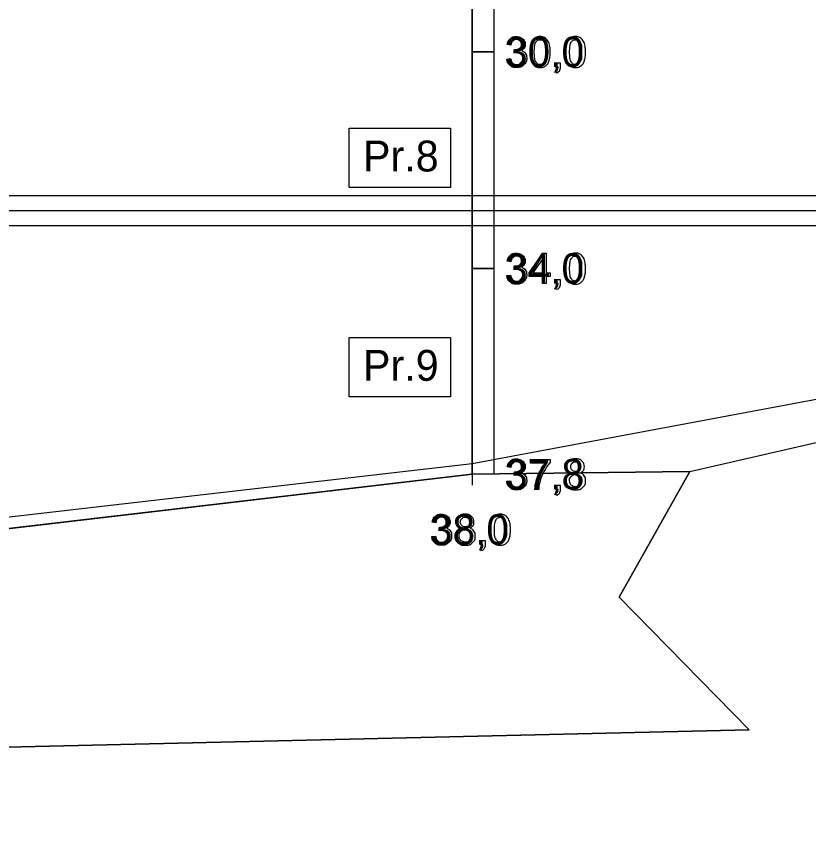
# Model space of a CAD drawing. Extents: x 700746 to 706058, y 6570320 to 6580460.
# Drawn here: x 705325.7 to 705472.1, y 6574755.4 to 6574905.5 of the extents above; entities that cross this region are included whole.
import ezdxf

# ---------------------------------------------------------------- set-up
doc = ezdxf.new("R2010")
doc.units = 0
for name, color, linetype in [('GEOLPUNKT', 7, 'Continuous'), ('GEOLPUNKT_proovid', 7, 'Continuous'), ('Maapind', 7, 'Continuous'), ('PIIR', 7, 'Continuous'), ('Plokid', 7, 'Continuous'), ('Täide', 7, 'Continuous')]:
    doc.layers.add(name, color=color, linetype=linetype)

msp = doc.modelspace()

# ---------------------------------------------------------------- linework, layer by layer
at = {"layer": 'GEOLPUNKT'}
msp.add_line((705409.93, 6574997.46), (705409.93, 6574818.93), dxfattribs=at)
for points in [[(705403.2, 6574811.95), (705402.51, 6574812.08)], [(705403.8, 6574810.56), (705403.87, 6574811.16)], [(705402.44, 6574809.39), (705403.13, 6574809.48)], [(705411.51, 6574807.91), (705411.51, 6574808.69), (705412.29, 6574808.69), (705412.29, 6574807.91)], [(705411.9, 6574807.91), (705411.51, 6574807.91)], [(705411.65, 6574806.8), (705411.46, 6574807.09)]]:
    msp.add_lwpolyline(points, dxfattribs=at)
for points in [[(705402.51, 6574812.08), (705402.64, 6574812.77), (705403.08, 6574813.15), (705403.53, 6574813.53), (705404.19, 6574813.53), (705404.65, 6574813.53), (705405.04, 6574813.33), (705405.43, 6574813.14), (705405.63, 6574812.8), (705405.83, 6574812.46), (705405.83, 6574812.08), (705405.83, 6574811.71), (705405.64, 6574811.42), (705405.44, 6574811.12), (705405.06, 6574810.94), (705405.56, 6574810.83), (705405.83, 6574810.47), (705406.11, 6574810.11), (705406.11, 6574809.57), (705406.11, 6574808.83), (705405.57, 6574808.32), (705405.04, 6574807.81), (705404.22, 6574807.81), (705403.48, 6574807.81), (705403, 6574808.25), (705402.51, 6574808.69), (705402.44, 6574809.39)], [(705407.85, 6574810.95), (705407.42, 6574811.1), (705407.21, 6574811.39), (705407, 6574811.68), (705407, 6574812.09), (705407, 6574812.7), (705407.44, 6574813.11), (705407.88, 6574813.53), (705408.61, 6574813.53), (705409.34, 6574813.53), (705409.79, 6574813.1), (705410.23, 6574812.68), (705410.23, 6574812.07), (705410.23, 6574811.68), (705410.03, 6574811.39), (705409.83, 6574811.1), (705409.41, 6574810.95), (705409.93, 6574810.78), (705410.2, 6574810.4), (705410.47, 6574810.03), (705410.47, 6574809.51), (705410.47, 6574808.79), (705409.96, 6574808.3), (705409.45, 6574807.81), (705408.62, 6574807.81), (705407.79, 6574807.81), (705407.29, 6574808.31), (705406.78, 6574808.8), (705406.78, 6574809.53), (705406.78, 6574810.08), (705407.06, 6574810.44), (705407.33, 6574810.81), (705407.85, 6574810.95)], [(705413.31, 6574810.67), (705413.31, 6574811.66), (705413.51, 6574812.27), (705413.72, 6574812.87), (705414.12, 6574813.2), (705414.52, 6574813.53), (705415.13, 6574813.53), (705415.58, 6574813.53), (705415.92, 6574813.35), (705416.26, 6574813.17), (705416.49, 6574812.83), (705416.71, 6574812.48), (705416.83, 6574811.99), (705416.96, 6574811.5), (705416.96, 6574810.67), (705416.96, 6574809.68), (705416.76, 6574809.08), (705416.55, 6574808.47), (705416.15, 6574808.14), (705415.75, 6574807.81), (705415.13, 6574807.81), (705414.32, 6574807.81), (705413.86, 6574808.39), (705413.31, 6574809.09), (705413.31, 6574810.67)], [(705403.87, 6574811.16), (705403.94, 6574811.16), (705403.98, 6574811.16), (705404.42, 6574811.16), (705404.77, 6574811.39), (705405.13, 6574811.62), (705405.13, 6574812.09), (705405.13, 6574812.47), (705404.87, 6574812.72), (705404.61, 6574812.97), (705404.21, 6574812.97), (705403.81, 6574812.97), (705403.54, 6574812.71), (705403.27, 6574812.46), (705403.2, 6574811.95)], [(705407.71, 6574812.11), (705407.71, 6574811.72), (705407.97, 6574811.46), (705408.22, 6574811.21), (705408.63, 6574811.21), (705409.02, 6574811.21), (705409.28, 6574811.46), (705409.53, 6574811.71), (705409.53, 6574812.07), (705409.53, 6574812.45), (705409.27, 6574812.71), (705409.01, 6574812.97), (705408.62, 6574812.97), (705408.23, 6574812.97), (705407.97, 6574812.71), (705407.71, 6574812.46), (705407.71, 6574812.11)], [(705414.02, 6574810.67), (705414.02, 6574809.29), (705414.34, 6574808.83), (705414.66, 6574808.38), (705415.13, 6574808.38), (705415.61, 6574808.38), (705415.93, 6574808.83), (705416.25, 6574809.29), (705416.25, 6574810.67), (705416.25, 6574812.05), (705415.93, 6574812.51), (705415.61, 6574812.96), (705415.13, 6574812.96), (705414.65, 6574812.96), (705414.37, 6574812.56), (705414.02, 6574812.05), (705414.02, 6574810.67)], [(705403.13, 6574809.48), (705403.25, 6574808.9), (705403.53, 6574808.64), (705403.81, 6574808.38), (705404.22, 6574808.38), (705404.71, 6574808.38), (705405.04, 6574808.72), (705405.38, 6574809.05), (705405.38, 6574809.55), (705405.38, 6574810.02), (705405.07, 6574810.33), (705404.76, 6574810.64), (705404.28, 6574810.64), (705404.09, 6574810.64), (705403.8, 6574810.56)], [(705407.49, 6574809.52), (705407.49, 6574809.23), (705407.62, 6574808.95), (705407.76, 6574808.68), (705408.04, 6574808.53), (705408.31, 6574808.38), (705408.63, 6574808.38), (705409.12, 6574808.38), (705409.44, 6574808.69), (705409.76, 6574809.01), (705409.76, 6574809.5), (705409.76, 6574810), (705409.43, 6574810.32), (705409.1, 6574810.65), (705408.6, 6574810.65), (705408.12, 6574810.65), (705407.8, 6574810.33), (705407.49, 6574810.01), (705407.49, 6574809.52)], [(705411.46, 6574807.09), (705411.68, 6574807.19), (705411.78, 6574807.37), (705411.88, 6574807.56), (705411.9, 6574807.91)], [(705412.29, 6574807.91), (705412.29, 6574807.48), (705412.14, 6574807.21), (705411.98, 6574806.94), (705411.65, 6574806.8)]]:
    msp.add_open_spline(points, degree=3, dxfattribs=at)
at = {"layer": 'GEOLPUNKT_proovid'}
for points in [[(705409.93, 6574948.93), (705413.93, 6574948.93), (705413.93, 6574898.93), (705409.93, 6574898.93)], [(705409.93, 6574898.93), (705413.93, 6574898.93), (705413.93, 6574858.93), (705409.93, 6574858.93)], [(705387.17, 6574884.82), (705405.87, 6574884.82), (705405.87, 6574873.86), (705387.17, 6574873.86)], [(705409.93, 6574858.93), (705413.93, 6574858.93), (705413.93, 6574820.93), (705409.93, 6574820.93)], [(705387.17, 6574846.17), (705405.87, 6574846.17), (705405.87, 6574835.21), (705387.17, 6574835.21)]]:
    msp.add_lwpolyline(points, close=True, dxfattribs=at)
for points in [[(705417.06, 6574900.18), (705416.38, 6574900.3)], [(705417.66, 6574898.78), (705417.74, 6574899.39)], [(705416.31, 6574897.61), (705417, 6574897.7)], [(705425.37, 6574896.13), (705425.37, 6574896.91), (705426.16, 6574896.91), (705426.16, 6574896.13)], [(705425.76, 6574896.13), (705425.37, 6574896.13)], [(705425.52, 6574895.02), (705425.33, 6574895.31)], [(705422.86, 6574856.13), (705422.86, 6574857.47), (705420.43, 6574857.47), (705420.43, 6574858.1), (705422.98, 6574861.73), (705423.54, 6574861.73), (705423.54, 6574858.1), (705424.3, 6574858.1), (705424.3, 6574857.47), (705423.54, 6574857.47), (705423.54, 6574856.13), (705422.86, 6574856.13)], [(705417.06, 6574860.18), (705416.38, 6574860.3)], [(705422.86, 6574858.1), (705422.86, 6574860.63), (705421.1, 6574858.1), (705422.86, 6574858.1)], [(705417.66, 6574858.78), (705417.74, 6574859.39)], [(705416.31, 6574857.61), (705417, 6574857.7)], [(705425.37, 6574856.13), (705425.37, 6574856.91), (705426.16, 6574856.91), (705426.16, 6574856.13)], [(705425.76, 6574856.13), (705425.37, 6574856.13)], [(705425.52, 6574855.02), (705425.33, 6574855.31)], [(705420.7, 6574822.99), (705420.7, 6574823.66), (705424.32, 6574823.66), (705424.32, 6574823.12)], [(705423.44, 6574822.99), (705420.7, 6574822.99)], [(705417.06, 6574822.18), (705416.38, 6574822.3)], [(705417.66, 6574820.78), (705417.74, 6574821.39)], [(705416.31, 6574819.61), (705417, 6574819.7)], [(705422.19, 6574818.13), (705421.48, 6574818.13)], [(705425.37, 6574818.13), (705425.37, 6574818.91), (705426.16, 6574818.91), (705426.16, 6574818.13)], [(705425.76, 6574818.13), (705425.37, 6574818.13)], [(705425.52, 6574817.02), (705425.33, 6574817.31)]]:
    msp.add_lwpolyline(points, dxfattribs=at)
for points in [[(705416.38, 6574900.3), (705416.5, 6574900.99), (705416.95, 6574901.37), (705417.4, 6574901.75), (705418.06, 6574901.75), (705418.52, 6574901.75), (705418.91, 6574901.55), (705419.29, 6574901.36), (705419.5, 6574901.02), (705419.7, 6574900.68), (705419.7, 6574900.3), (705419.7, 6574899.94), (705419.51, 6574899.64), (705419.31, 6574899.34), (705418.93, 6574899.16), (705419.43, 6574899.05), (705419.7, 6574898.69), (705419.97, 6574898.33), (705419.97, 6574897.79), (705419.97, 6574897.05), (705419.44, 6574896.54), (705418.91, 6574896.04), (705418.09, 6574896.04), (705417.35, 6574896.04), (705416.86, 6574896.47), (705416.38, 6574896.91), (705416.31, 6574897.61)], [(705417.74, 6574899.39), (705417.81, 6574899.38), (705417.85, 6574899.38), (705418.29, 6574899.38), (705418.64, 6574899.61), (705418.99, 6574899.84), (705418.99, 6574900.31), (705418.99, 6574900.69), (705418.74, 6574900.94), (705418.48, 6574901.19), (705418.08, 6574901.19), (705417.67, 6574901.19), (705417.41, 6574900.93), (705417.14, 6574900.68), (705417.06, 6574900.18)], [(705420.65, 6574898.89), (705420.65, 6574899.88), (705420.86, 6574900.49), (705421.06, 6574901.1), (705421.46, 6574901.42), (705421.87, 6574901.75), (705422.48, 6574901.75), (705422.93, 6574901.75), (705423.27, 6574901.57), (705423.61, 6574901.39), (705423.83, 6574901.05), (705424.05, 6574900.7), (705424.18, 6574900.21), (705424.3, 6574899.72), (705424.3, 6574898.89), (705424.3, 6574897.91), (705424.1, 6574897.3), (705423.9, 6574896.69), (705423.5, 6574896.36), (705423.09, 6574896.04), (705422.48, 6574896.04), (705421.67, 6574896.04), (705421.21, 6574896.61), (705420.65, 6574897.31), (705420.65, 6574898.89)], [(705421.36, 6574898.89), (705421.36, 6574897.51), (705421.68, 6574897.05), (705422.01, 6574896.6), (705422.48, 6574896.6), (705422.95, 6574896.6), (705423.27, 6574897.06), (705423.59, 6574897.51), (705423.59, 6574898.89), (705423.59, 6574900.27), (705423.27, 6574900.73), (705422.95, 6574901.18), (705422.47, 6574901.18), (705422, 6574901.18), (705421.71, 6574900.78), (705421.36, 6574900.27), (705421.36, 6574898.89)], [(705427.18, 6574898.89), (705427.18, 6574899.88), (705427.38, 6574900.49), (705427.58, 6574901.1), (705427.99, 6574901.42), (705428.39, 6574901.75), (705429, 6574901.75), (705429.45, 6574901.75), (705429.79, 6574901.57), (705430.13, 6574901.39), (705430.35, 6574901.05), (705430.57, 6574900.7), (705430.7, 6574900.21), (705430.82, 6574899.72), (705430.82, 6574898.89), (705430.82, 6574897.91), (705430.62, 6574897.3), (705430.42, 6574896.69), (705430.02, 6574896.36), (705429.61, 6574896.04), (705429, 6574896.04), (705428.19, 6574896.04), (705427.73, 6574896.61), (705427.18, 6574897.31), (705427.18, 6574898.89)], [(705427.88, 6574898.89), (705427.88, 6574897.51), (705428.21, 6574897.05), (705428.53, 6574896.6), (705429, 6574896.6), (705429.47, 6574896.6), (705429.79, 6574897.06), (705430.12, 6574897.51), (705430.12, 6574898.89), (705430.12, 6574900.27), (705429.79, 6574900.73), (705429.47, 6574901.18), (705428.99, 6574901.18), (705428.52, 6574901.18), (705428.24, 6574900.78), (705427.88, 6574900.27), (705427.88, 6574898.89)], [(705417, 6574897.7), (705417.11, 6574897.12), (705417.4, 6574896.86), (705417.68, 6574896.6), (705418.09, 6574896.6), (705418.58, 6574896.6), (705418.91, 6574896.94), (705419.24, 6574897.27), (705419.24, 6574897.77), (705419.24, 6574898.25), (705418.94, 6574898.55), (705418.63, 6574898.86), (705418.15, 6574898.86), (705417.95, 6574898.86), (705417.66, 6574898.78)], [(705425.33, 6574895.31), (705425.54, 6574895.41), (705425.65, 6574895.6), (705425.75, 6574895.78), (705425.76, 6574896.13)], [(705426.16, 6574896.13), (705426.16, 6574895.7), (705426, 6574895.43), (705425.85, 6574895.16), (705425.52, 6574895.02)], [(705416.38, 6574860.3), (705416.5, 6574860.99), (705416.95, 6574861.37), (705417.4, 6574861.75), (705418.06, 6574861.75), (705418.52, 6574861.75), (705418.91, 6574861.55), (705419.29, 6574861.36), (705419.5, 6574861.02), (705419.7, 6574860.68), (705419.7, 6574860.3), (705419.7, 6574859.94), (705419.51, 6574859.64), (705419.31, 6574859.34), (705418.93, 6574859.16), (705419.43, 6574859.05), (705419.7, 6574858.69), (705419.97, 6574858.33), (705419.97, 6574857.79), (705419.97, 6574857.05), (705419.44, 6574856.54), (705418.91, 6574856.04), (705418.09, 6574856.04), (705417.35, 6574856.04), (705416.86, 6574856.47), (705416.38, 6574856.91), (705416.31, 6574857.61)], [(705427.18, 6574858.89), (705427.18, 6574859.88), (705427.38, 6574860.49), (705427.58, 6574861.1), (705427.99, 6574861.42), (705428.39, 6574861.75), (705429, 6574861.75), (705429.45, 6574861.75), (705429.79, 6574861.57), (705430.13, 6574861.39), (705430.35, 6574861.05), (705430.57, 6574860.7), (705430.7, 6574860.21), (705430.82, 6574859.72), (705430.82, 6574858.89), (705430.82, 6574857.91), (705430.62, 6574857.3), (705430.42, 6574856.69), (705430.02, 6574856.36), (705429.61, 6574856.04), (705429, 6574856.04), (705428.19, 6574856.04), (705427.73, 6574856.61), (705427.18, 6574857.31), (705427.18, 6574858.89)], [(705417.74, 6574859.39), (705417.81, 6574859.38), (705417.85, 6574859.38), (705418.29, 6574859.38), (705418.64, 6574859.61), (705418.99, 6574859.84), (705418.99, 6574860.31), (705418.99, 6574860.69), (705418.74, 6574860.94), (705418.48, 6574861.19), (705418.08, 6574861.19), (705417.67, 6574861.19), (705417.41, 6574860.93), (705417.14, 6574860.68), (705417.06, 6574860.18)], [(705427.88, 6574858.89), (705427.88, 6574857.51), (705428.21, 6574857.05), (705428.53, 6574856.6), (705429, 6574856.6), (705429.47, 6574856.6), (705429.79, 6574857.06), (705430.12, 6574857.51), (705430.12, 6574858.89), (705430.12, 6574860.27), (705429.79, 6574860.73), (705429.47, 6574861.18), (705428.99, 6574861.18), (705428.52, 6574861.18), (705428.24, 6574860.78), (705427.88, 6574860.27), (705427.88, 6574858.89)], [(705417, 6574857.7), (705417.11, 6574857.12), (705417.4, 6574856.86), (705417.68, 6574856.6), (705418.09, 6574856.6), (705418.58, 6574856.6), (705418.91, 6574856.94), (705419.24, 6574857.27), (705419.24, 6574857.77), (705419.24, 6574858.25), (705418.94, 6574858.55), (705418.63, 6574858.86), (705418.15, 6574858.86), (705417.95, 6574858.86), (705417.66, 6574858.78)], [(705425.33, 6574855.31), (705425.54, 6574855.41), (705425.65, 6574855.6), (705425.75, 6574855.78), (705425.76, 6574856.13)], [(705426.16, 6574856.13), (705426.16, 6574855.7), (705426, 6574855.43), (705425.85, 6574855.16), (705425.52, 6574855.02)], [(705416.38, 6574822.3), (705416.5, 6574822.99), (705416.95, 6574823.37), (705417.4, 6574823.75), (705418.06, 6574823.75), (705418.52, 6574823.75), (705418.91, 6574823.55), (705419.29, 6574823.36), (705419.5, 6574823.02), (705419.7, 6574822.68), (705419.7, 6574822.3), (705419.7, 6574821.94), (705419.51, 6574821.64), (705419.31, 6574821.34), (705418.93, 6574821.16), (705419.43, 6574821.05), (705419.7, 6574820.69), (705419.97, 6574820.33), (705419.97, 6574819.79), (705419.97, 6574819.05), (705419.44, 6574818.54), (705418.91, 6574818.04), (705418.09, 6574818.04), (705417.35, 6574818.04), (705416.86, 6574818.47), (705416.38, 6574818.91), (705416.31, 6574819.61)], [(705417.74, 6574821.39), (705417.81, 6574821.38), (705417.85, 6574821.38), (705418.29, 6574821.38), (705418.64, 6574821.61), (705418.99, 6574821.84), (705418.99, 6574822.31), (705418.99, 6574822.69), (705418.74, 6574822.94), (705418.48, 6574823.19), (705418.08, 6574823.19), (705417.67, 6574823.19), (705417.41, 6574822.93), (705417.14, 6574822.68), (705417.06, 6574822.18)], [(705421.48, 6574818.13), (705421.49, 6574818.79), (705421.74, 6574819.73), (705421.99, 6574820.66), (705422.45, 6574821.53), (705422.92, 6574822.4), (705423.44, 6574822.99)], [(705424.32, 6574823.12), (705423.79, 6574822.55), (705423.26, 6574821.61), (705422.74, 6574820.66), (705422.45, 6574819.67), (705422.25, 6574818.97), (705422.19, 6574818.13)], [(705428.24, 6574821.17), (705427.81, 6574821.32), (705427.6, 6574821.61), (705427.39, 6574821.9), (705427.39, 6574822.31), (705427.39, 6574822.92), (705427.83, 6574823.33), (705428.27, 6574823.75), (705429, 6574823.75), (705429.73, 6574823.75), (705430.18, 6574823.33), (705430.62, 6574822.9), (705430.62, 6574822.29), (705430.62, 6574821.9), (705430.42, 6574821.61), (705430.21, 6574821.32), (705429.8, 6574821.17), (705430.31, 6574821), (705430.58, 6574820.63), (705430.85, 6574820.25), (705430.85, 6574819.73), (705430.85, 6574819.01), (705430.35, 6574818.52), (705429.84, 6574818.04), (705429.01, 6574818.04), (705428.18, 6574818.04), (705427.67, 6574818.53), (705427.17, 6574819.02), (705427.17, 6574819.75), (705427.17, 6574820.3), (705427.45, 6574820.67), (705427.72, 6574821.03), (705428.24, 6574821.17)], [(705428.1, 6574822.33), (705428.1, 6574821.94), (705428.35, 6574821.68), (705428.61, 6574821.43), (705429.02, 6574821.43), (705429.41, 6574821.43), (705429.66, 6574821.68), (705429.92, 6574821.93), (705429.92, 6574822.29), (705429.92, 6574822.67), (705429.66, 6574822.93), (705429.4, 6574823.19), (705429.01, 6574823.19), (705428.62, 6574823.19), (705428.36, 6574822.94), (705428.1, 6574822.68), (705428.1, 6574822.33)], [(705417, 6574819.7), (705417.11, 6574819.12), (705417.4, 6574818.86), (705417.68, 6574818.6), (705418.09, 6574818.6), (705418.58, 6574818.6), (705418.91, 6574818.94), (705419.24, 6574819.27), (705419.24, 6574819.77), (705419.24, 6574820.25), (705418.94, 6574820.55), (705418.63, 6574820.86), (705418.15, 6574820.86), (705417.95, 6574820.86), (705417.66, 6574820.78)], [(705427.88, 6574819.75), (705427.88, 6574819.45), (705428.01, 6574819.18), (705428.15, 6574818.9), (705428.43, 6574818.75), (705428.7, 6574818.6), (705429.02, 6574818.6), (705429.51, 6574818.6), (705429.83, 6574818.92), (705430.15, 6574819.23), (705430.15, 6574819.72), (705430.15, 6574820.22), (705429.82, 6574820.54), (705429.49, 6574820.87), (705428.99, 6574820.87), (705428.51, 6574820.87), (705428.19, 6574820.55), (705427.88, 6574820.23), (705427.88, 6574819.75)], [(705425.33, 6574817.31), (705425.54, 6574817.41), (705425.65, 6574817.6), (705425.75, 6574817.78), (705425.76, 6574818.13)], [(705426.16, 6574818.13), (705426.16, 6574817.7), (705426, 6574817.43), (705425.85, 6574817.16), (705425.52, 6574817.02)]]:
    msp.add_open_spline(points, degree=3, dxfattribs=at)
at = {"layer": 'Maapind'}
msp.add_line((705450.07, 6574821.41), (705658.33, 6574869.28), dxfattribs=at)
for points in [[(705450.07, 6574821.41), (705437.02, 6574798.19), (705461.03, 6574773.73), (705273.78, 6574769.37), (705123.86, 6574755.44), (705160.71, 6574778.36), (705118.38, 6574794.81)], [(705450.07, 6574821.41), (705409.93, 6574820.93), (705189.33, 6574795.03), (705170.55, 6574793.33), (705118.38, 6574794.81)]]:
    msp.add_lwpolyline(points, dxfattribs=at)
at = {"layer": 'PIIR'}
msp.add_lwpolyline([(704401.55, 6574869.63), (705660.11, 6574869.63)], dxfattribs=at)
at = {"layer": 'Plokid'}
for p, q in [((704401.55, 6574872.38), (705659.86, 6574872.38)), ((704146.26, 6574866.83), (705645.04, 6574866.83))]:
    msp.add_line(p, q, dxfattribs=at)
msp.add_lwpolyline([(704399.9, 6574813.93), (704646.39, 6574838.03), (704915.95, 6574846.43), (705118.38, 6574796.88), (705170.55, 6574795.33), (705409.93, 6574822.93), (705409.93, 6574822.93), (705409.93, 6574822.93), (705645.04, 6574866.83)], dxfattribs=at)
at = {"layer": 'Täide'}
for p, q in [((705450.07, 6574821.41), (705658.33, 6574869.28)), ((705450.07, 6574821.41), (705409.93, 6574820.93)), ((705409.93, 6574820.93), (705450.07, 6574821.41)), ((705409.93, 6574820.93), (705189.33, 6574795.03)), ((705189.33, 6574795.03), (705409.93, 6574820.93))]:
    msp.add_line(p, q, dxfattribs=at)
for points in [[(704720.42, 6574838.24), (704915.95, 6574844.43), (705118.38, 6574794.81), (705170.55, 6574793.33), (705189.33, 6574795.03), (705409.93, 6574820.93), (705450.07, 6574821.41), (705658.33, 6574869.28)], [(705118.38, 6574794.81), (705160.71, 6574778.36), (705123.86, 6574755.44), (705273.78, 6574769.37), (705461.03, 6574773.73), (705437.02, 6574798.19), (705450.07, 6574821.41)]]:
    msp.add_lwpolyline(points, dxfattribs=at)

# ---------------------------------------------------------------- texts
at = {"layer": 'GEOLPUNKT'}
msp.add_text('38,0', height=5.6, dxfattribs=at).set_placement((705402.11, 6574807.91))
at = {"layer": 'GEOLPUNKT_proovid'}
for s, height, p in [('30,0', 5.6, (705415.98, 6574896.13)), ('Pr.8', 5.7, (705389.73, 6574876.84)), ('34,0', 5.6, (705415.98, 6574856.13)), ('Pr.9', 5.7, (705389.73, 6574838.18)), ('37,8', 5.6, (705415.98, 6574818.13))]:
    msp.add_text(s, height=height, dxfattribs=at).set_placement(p)

doc.saveas('drawing.dxf')
